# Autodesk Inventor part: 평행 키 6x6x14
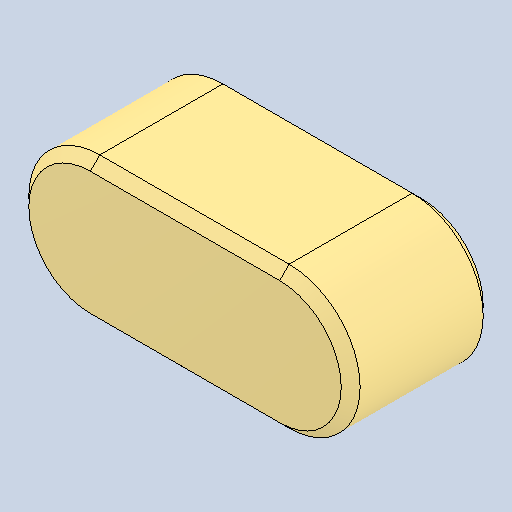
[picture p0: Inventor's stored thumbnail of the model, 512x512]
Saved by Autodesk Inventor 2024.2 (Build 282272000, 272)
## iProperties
Created: 2025-09
Part Number: 평행 키 6x6x14
Material: 강철, 연강
Description: 키 및 해당 키홈
Document SubType Name: Modeling
Designer: home
Density: 7.85 g/cm^3
Appearance: 기본값
Author: jhkim
Sending System: Autodesk Inventor 2026
Preprocessor: ST-DEVELOPER v20.1
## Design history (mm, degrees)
feature "Solid1"
node "솔리드1"
